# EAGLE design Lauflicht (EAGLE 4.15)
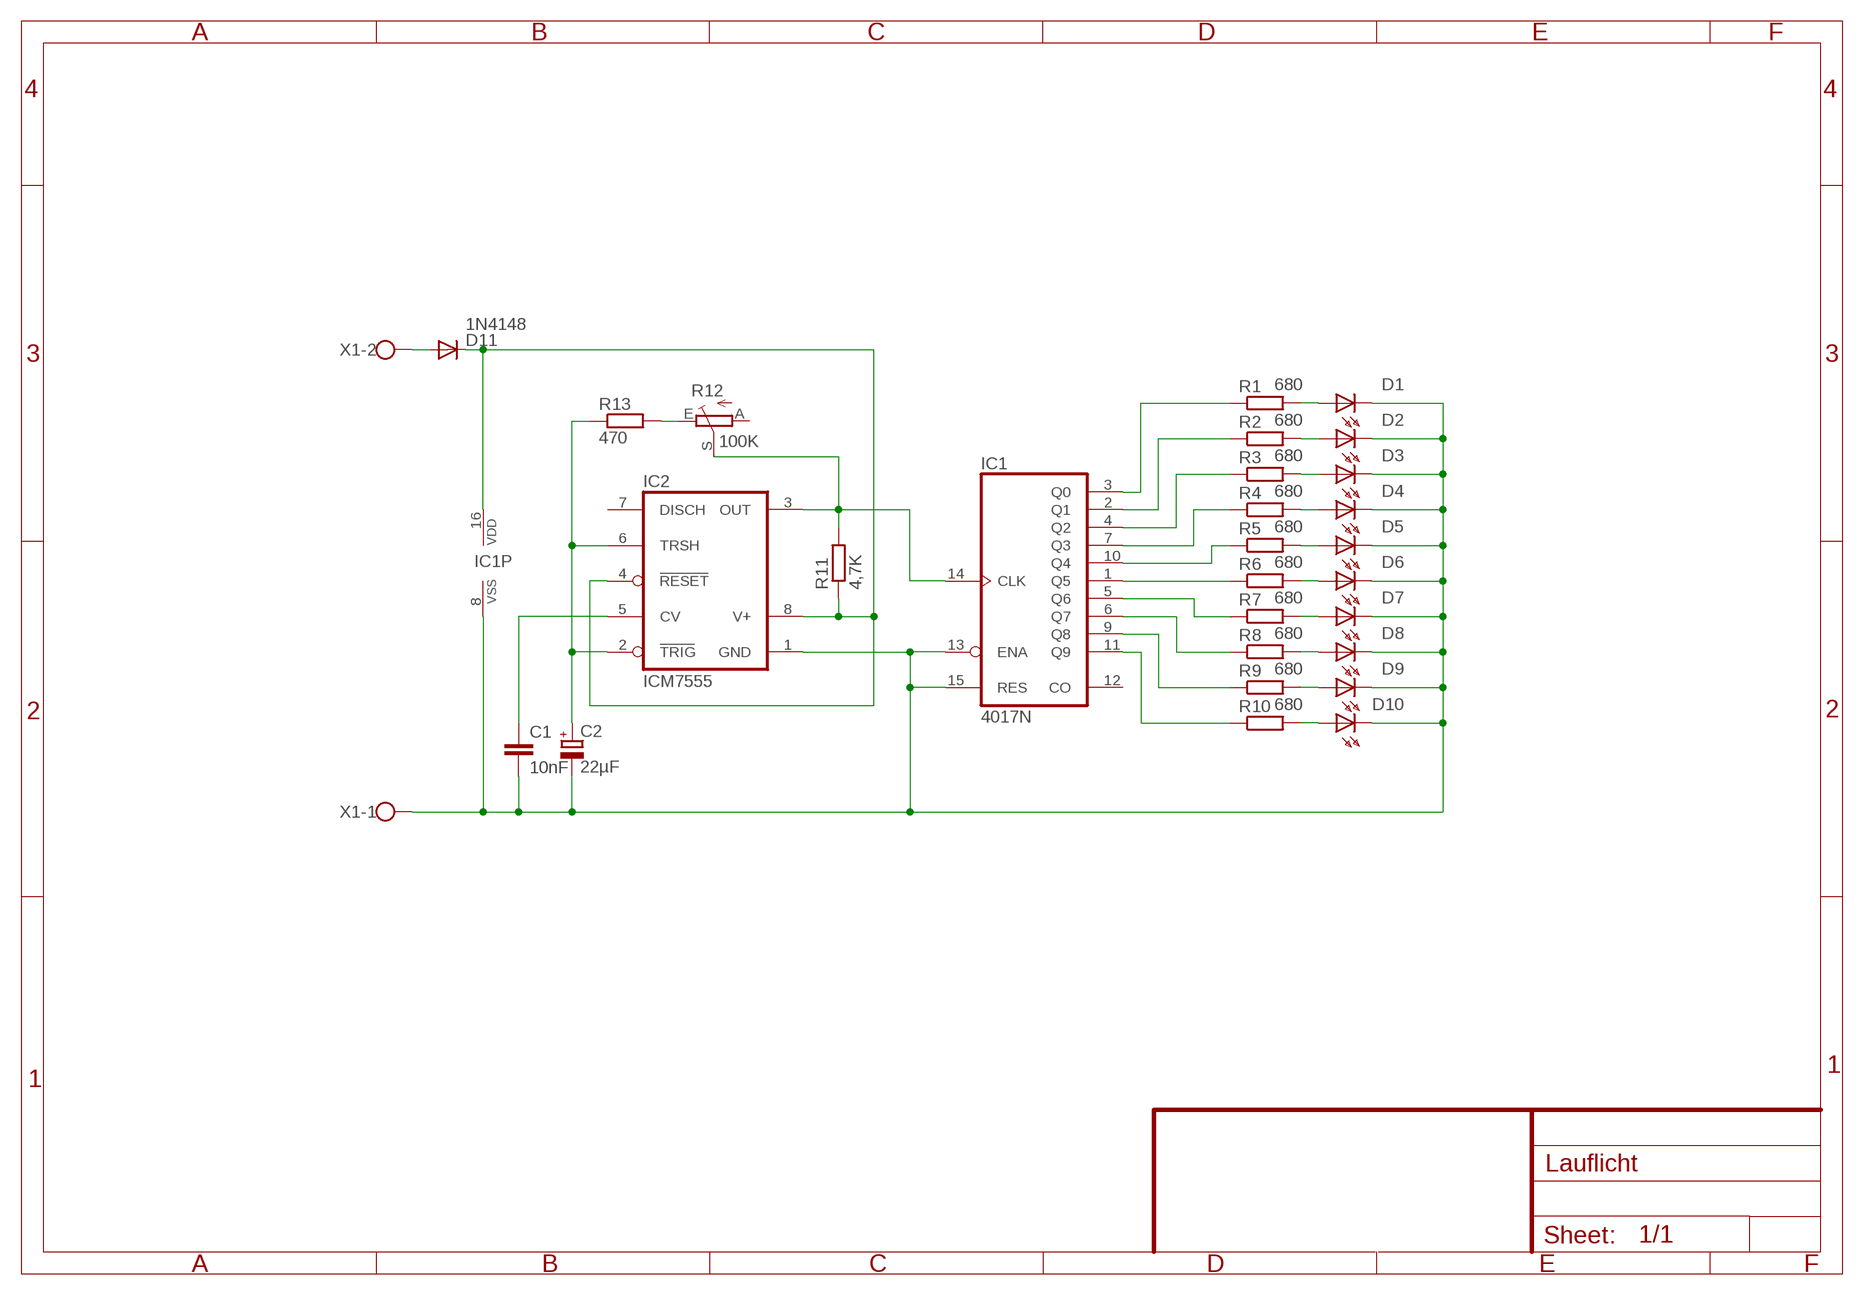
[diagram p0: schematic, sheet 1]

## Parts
C1  10nF  C-EU025-030X050  [C025-030X050]
C2  22µF  CPOL-EUE2.5-6  [E2,5-6]
D1  LED5MM  [LED5MM]
D2  LED5MM  [LED5MM]
D3  LED5MM  [LED5MM]
D4  LED5MM  [LED5MM]
D5  LED5MM  [LED5MM]
D6  LED5MM  [LED5MM]
D7  LED5MM  [LED5MM]
D8  LED5MM  [LED5MM]
D9  LED5MM  [LED5MM]
D10  LED5MM  [LED5MM]
D11  1N4148  1N4004  [DO41-10]
IC1  4017N  [DIL16]
IC2  ICM7555  [DIL08]
R1  680  R-EU_0207/10  [0207/10]
R2  680  R-EU_0207/10  [0207/10]
R3  680  R-EU_0207/10  [0207/10]
R4  680  R-EU_0207/10  [0207/10]
R5  680  R-EU_0207/10  [0207/10]
R6  680  R-EU_0207/10  [0207/10]
R7  680  R-EU_0207/10  [0207/10]
R8  680  R-EU_0207/10  [0207/10]
R9  680  R-EU_0207/10  [0207/10]
R10  680  R-EU_0207/10  [0207/10]
R11  4,7K  R-EU_0207/10  [0207/10]
R12  100K  TRIM_EU-LI10  [LI10]
R13  470  R-EU_0207/10  [0207/10]
X1  W237-102  [W237-102]

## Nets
GND: C1.2 C2.- D1.K(C) D2.K(C) D3.K(C) D4.K(C) D5.K(C) D6.K(C) D7.K(C) D8.K(C) D9.K(C) D10.K(C) IC1.8(VSS) IC1.13(ENA) IC1.15(RES) IC2.1(GND) X1.1
N$1: IC1.11(Q9) R10.1
N$2: IC1.9(Q8) R9.1
N$3: IC1.6(Q7) R8.1
N$4: IC1.5(Q6) R7.1
N$5: IC1.1(Q5) R6.1
N$6: IC1.10(Q4) R5.1
N$7: IC1.7(Q3) R4.1
N$8: IC1.4(Q2) R3.1
N$9: IC1.2(Q1) R2.1
N$10: IC1.3(Q0) R1.1
N$11: D1.A R1.2
N$12: D2.A R2.2
N$13: D3.A R3.2
N$14: D4.A R4.2
N$15: D5.A R5.2
N$16: D9.A R9.2
N$17: D10.A R10.2
N$18: D8.A R8.2
N$19: D7.A R7.2
N$20: D6.A R6.2
N$21: C2.+ IC2.2(TRIG) IC2.6(TRSH) R13.1
N$22: D11.A X1.2
N$23: IC1.14(CLK) IC2.3(OUT) R11.2 R12.S
N$24: C1.1 IC2.5(CV)
N$25: D11.C IC1.16(VDD) IC2.4(RESET) IC2.8(V+) R11.1
N$26: R12.E R13.2
Unconnected: IC1.12(CO) IC2.7(DISCH) R12.A

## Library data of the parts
C1 = rcl:C-EU: CAPACITOR, European symbol
C2 = rcl:CPOL-EU: POLARIZED CAPACITOR, European symbol
D1-D10 = led:LED5MM: LED
D11 = diode:1N4004: DIODE
IC1 = 40xx:4017: COUNTER/DIVIDER
IC2 = maxim:ICM7555: TIMER
R1-R11 R13 = rcl:R-EU_: RESISTOR, European symbol
R12 = pot:TRIM_EU-: POTENTIOMETER
X1 = con-wago-500:W237-102: WAGO SCREW CLAMP

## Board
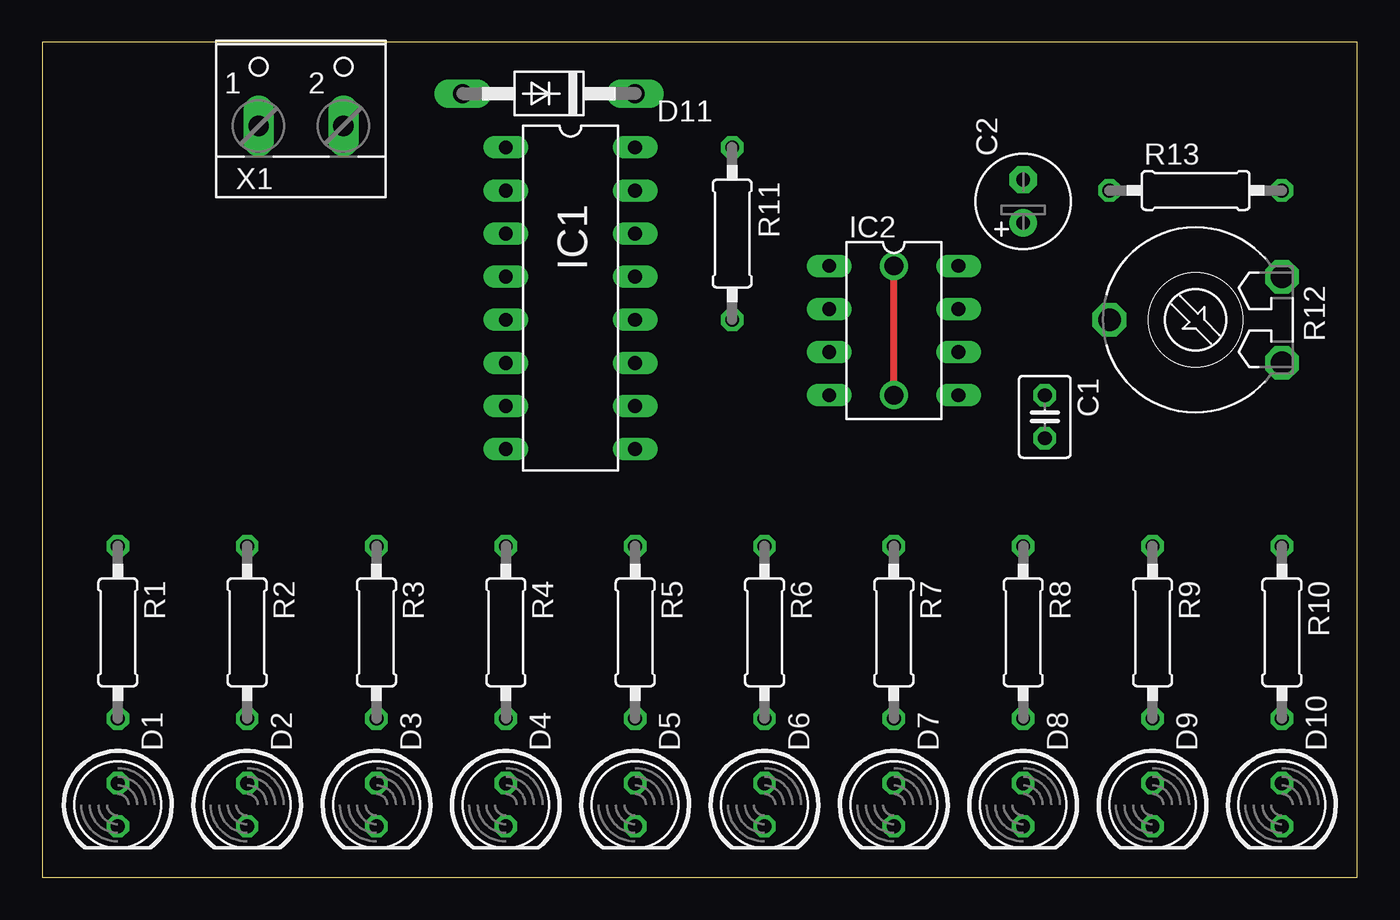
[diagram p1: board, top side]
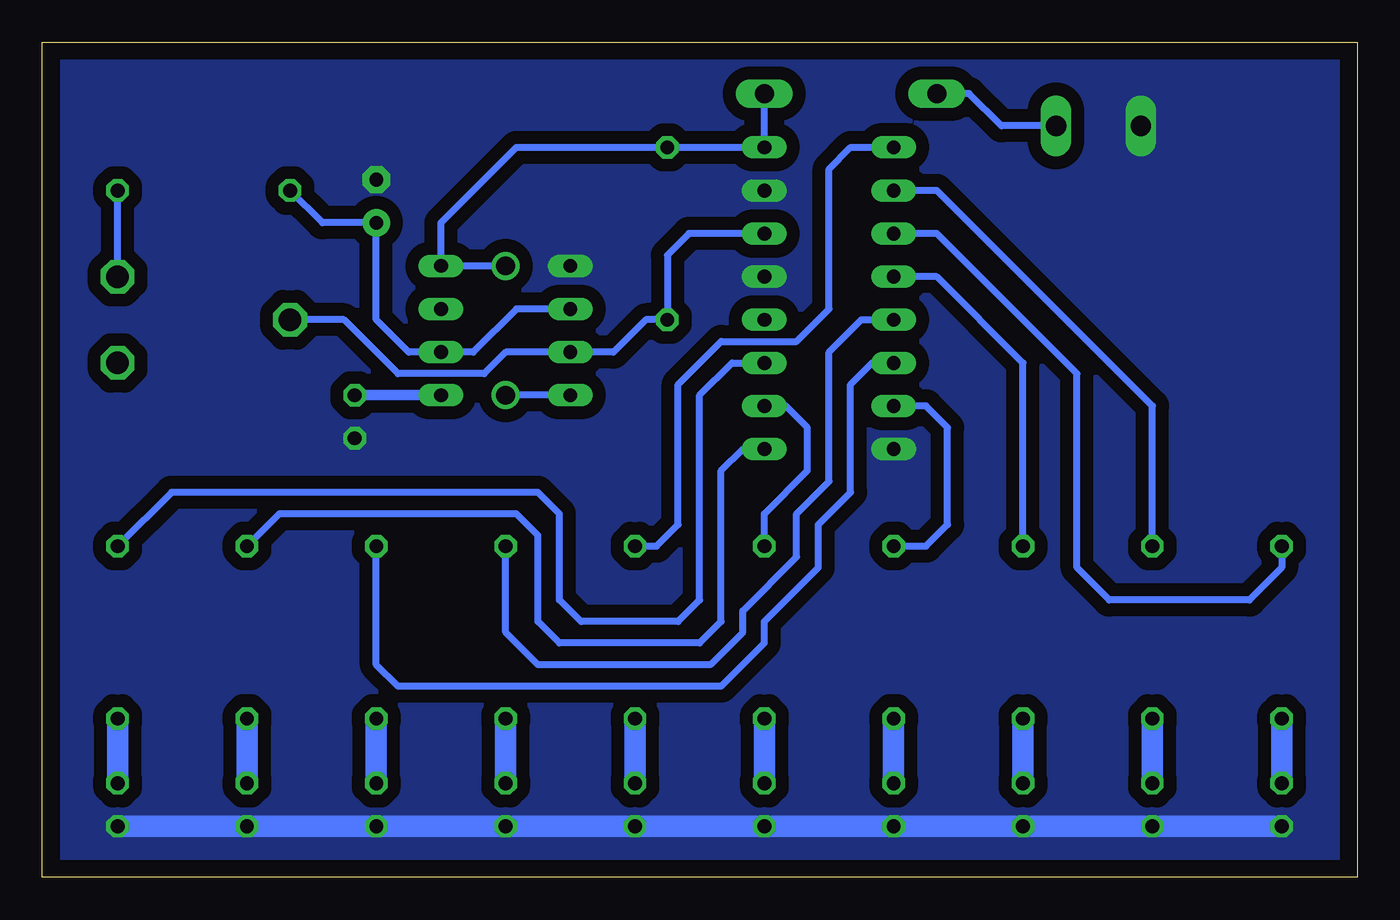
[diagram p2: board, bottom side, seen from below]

Size 77.45 x 49.2 mm. Coordinates in mm from the lower left corner, seen from the top.
Outline: 0,0 77.45,0 77.45,49.2 0,49.2 0,0
Copper layers (1*16): Top 0.035mm / dielectric 1.5mm / Bottom 0.035mm
Design rules "default": minimum track width 10mil, minimum drill 24mil, track to track 8mil, track to pad 8mil, pad to pad 8mil, via to via 8mil, smd to smd 8mil, copper to edge 40mil, drill to drill 8mil, minimum pad ring 10mil, minimum via ring 8mil, stop-mask expansion 4mil, vias tented up to drill 0mil, thermal gap 10mil

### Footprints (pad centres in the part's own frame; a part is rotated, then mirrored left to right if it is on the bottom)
C025-030X050 = drill 0.813 octagon: 1 -1.27,0; 2 1.27,0
E2,5-6 = drill 0.813 pad 1.6 round: + -1.27,0 | drill 0.813 pad 1.6 octagon: - 1.27,0
LED5MM = drill 0.813 octagon: A -1.27,0; K 1.27,0
DO41-10 = drill 1.118 long: A 5.08,0; C -5.08,0
DIL16 = drill 0.813 long: 1 -8.89,-3.81; 2 -6.35,-3.81; 3 -3.81,-3.81; 4 -1.27,-3.81; 5 1.27,-3.81; 6 3.81,-3.81; 7 6.35,-3.81; 8 8.89,-3.81; 9 8.89,3.81; 10 6.35,3.81; 11 3.81,3.81; 12 1.27,3.81; 13 -1.27,3.81; 14 -3.81,3.81; 15 -6.35,3.81; 16 -8.89,3.81
DIL08 = drill 0.813 long: 1 -3.81,-3.81; 2 -1.27,-3.81; 3 1.27,-3.81; 4 3.81,-3.81; 5 3.81,3.81; 6 1.27,3.81; 7 -1.27,3.81; 8 -3.81,3.81
0207/10 = drill 0.813 octagon: 1 -5.08,0; 2 5.08,0
LI10 = drill 1.321 octagon: A -2.54,-5.08; E 2.54,-5.08; S 0,5.08
W237-102 = drill 1.194 long: 1 -2.5,-1.27; 2 2.5,-1.27

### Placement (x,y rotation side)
C1  59.05,27.14 270 top
C2  57.78,39.84 90 top
D1  4.44,4.28 270 top
D2  12.06,4.28 270 top
D3  19.68,4.28 270 top
D4  27.3,4.28 270 top
D5  34.92,4.28 270 top
D6  42.54,4.28 270 top
D7  50.16,4.28 270 top
D8  57.78,4.28 270 top
D9  65.4,4.28 270 top
D10  73.02,4.28 270 top
D11  29.84,46.19 180 top
IC1  31.11,34.12 270 top
IC2  50.16,32.22 270 top
R1  4.44,14.44 270 top
R2  12.06,14.44 270 top
R3  19.68,14.44 270 top
R4  27.3,14.44 270 top
R5  34.92,14.44 270 top
R6  42.54,14.44 270 top
R7  50.16,14.44 270 top
R8  57.78,14.44 270 top
R9  65.4,14.44 270 top
R10  73.02,14.44 270 top
R11  40.63,37.94 270 top
R12  67.94,32.86 90 top
R13  67.94,40.48 0 top
X1  15.23,45.55 0 top

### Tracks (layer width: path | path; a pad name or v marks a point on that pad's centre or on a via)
GND
  Bottom 1.27: D10.K D9.K D8.K D7.K D6.K D5.K D4.K D3.K D2.K D1.K
  pour Bottom (isolate 0.762, no thermals): 0.63,0.47 0.63,48.73 76.83,48.73 76.83,0.47
N$1
  Bottom 0.406: IC1.11 36.82,30.32 38.73,28.41 38.73,16.35 40,15.08 45.71,15.08 46.98,16.35 46.98,21.43 48.25,22.7 69.84,22.7 R10.1
N$2
  Bottom 0.406: IC1.9 36.19,25.23 37.46,23.96 37.46,15.08 38.73,13.81 46.98,13.81 48.25,15.08 48.25,20.16 49.52,21.43 63.49,21.43 R9.1
N$3
  Bottom 0.406: IC1.6 28.57,30.32 29.84,29.05 29.84,22.7 31.75,20.79 31.75,18.25 34.92,15.08 34.92,13.81 37.46,11.27 56.51,11.27 57.78,12.54 R8.1
N$4
  Bottom 0.406: IC1.5 29.21,32.86 31.11,30.95 31.11,23.33 33.02,21.43 33.02,18.89 36.19,15.71 36.19,14.44 38.09,12.54 48.25,12.54 50.16,14.44 R7.1
N$5
  Bottom 0.406: IC1.1 29.84,43.02 31.11,41.74 31.11,33.49 33.02,31.59 37.46,31.59 40,29.05 40,20.79 41.27,19.52 R6.1
N$6
  Bottom 0.406: IC1.10 33.65,27.78 32.38,26.51 32.38,23.96 34.92,21.43 R5.1
N$7
  Bottom 0.406: IC1.7 25.39,27.78 24.12,26.51 24.12,20.79 25.39,19.52 R4.1
N$8
  Bottom 0.406: R3.1 19.68,30.32 24.76,35.4 IC1.4
N$9
  Bottom 0.406: R2.1 12.06,27.78 24.76,40.48 IC1.2
N$10
  Bottom 0.406: R1.1 4.44,18.25 6.34,16.35 14.6,16.35 16.51,18.25 16.51,29.68 24.76,37.94 IC1.3
N$11
  Bottom 1.27: D1.A R1.2
N$12
  Bottom 1.27: D2.A R2.2
N$13
  Bottom 1.27: D3.A R3.2
N$14
  Bottom 1.27: D4.A R4.2
N$15
  Bottom 1.27: D5.A R5.2
N$16
  Bottom 1.27: D9.A R9.2
N$17
  Bottom 1.27: D10.A R10.2
N$18
  Bottom 1.27: D8.A R8.2
N$19
  Bottom 1.27: D7.A R7.2
N$20
  Bottom 1.27: D6.A R6.2
N$21
  Bottom 0.406: R13.1 60.95,38.57 C2.+ 57.78,32.86 55.88,30.95 IC2.6 52.06,30.95 49.52,33.49 IC2.2
N$22
  Bottom 0.406: X1.2 20.95,44.29 22.86,46.19 D11.A
N$23
  Bottom 0.406: IC1.14 39.36,37.94 40.63,36.66 R11.2 41.9,32.86 43.81,30.95 IC2.3 50.16,30.95 51.43,29.68 56.51,29.68 59.68,32.86 R12.S
N$24
  Bottom 0.61: IC2.5 C1.1
N$25  (via drill 1.1)
  Top 0.406: v50.16,28.41 v50.16,36.03
  Bottom 0.406: IC2.4 v50.16,28.41 | v50.16,36.03 IC2.8 53.97,38.57 49.52,43.02 R11.1 IC1.16 D11.C
N$26
  Bottom 0.406: R12.E R13.2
